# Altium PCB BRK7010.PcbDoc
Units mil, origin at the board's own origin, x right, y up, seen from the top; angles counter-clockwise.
Board outline 4724.41 x 3149.61 mil, 2 copper layers (Top Layer, Bottom Layer), stack 60.5 mil thick; 29 components, 139 nets, 372 pads, 81 vias.
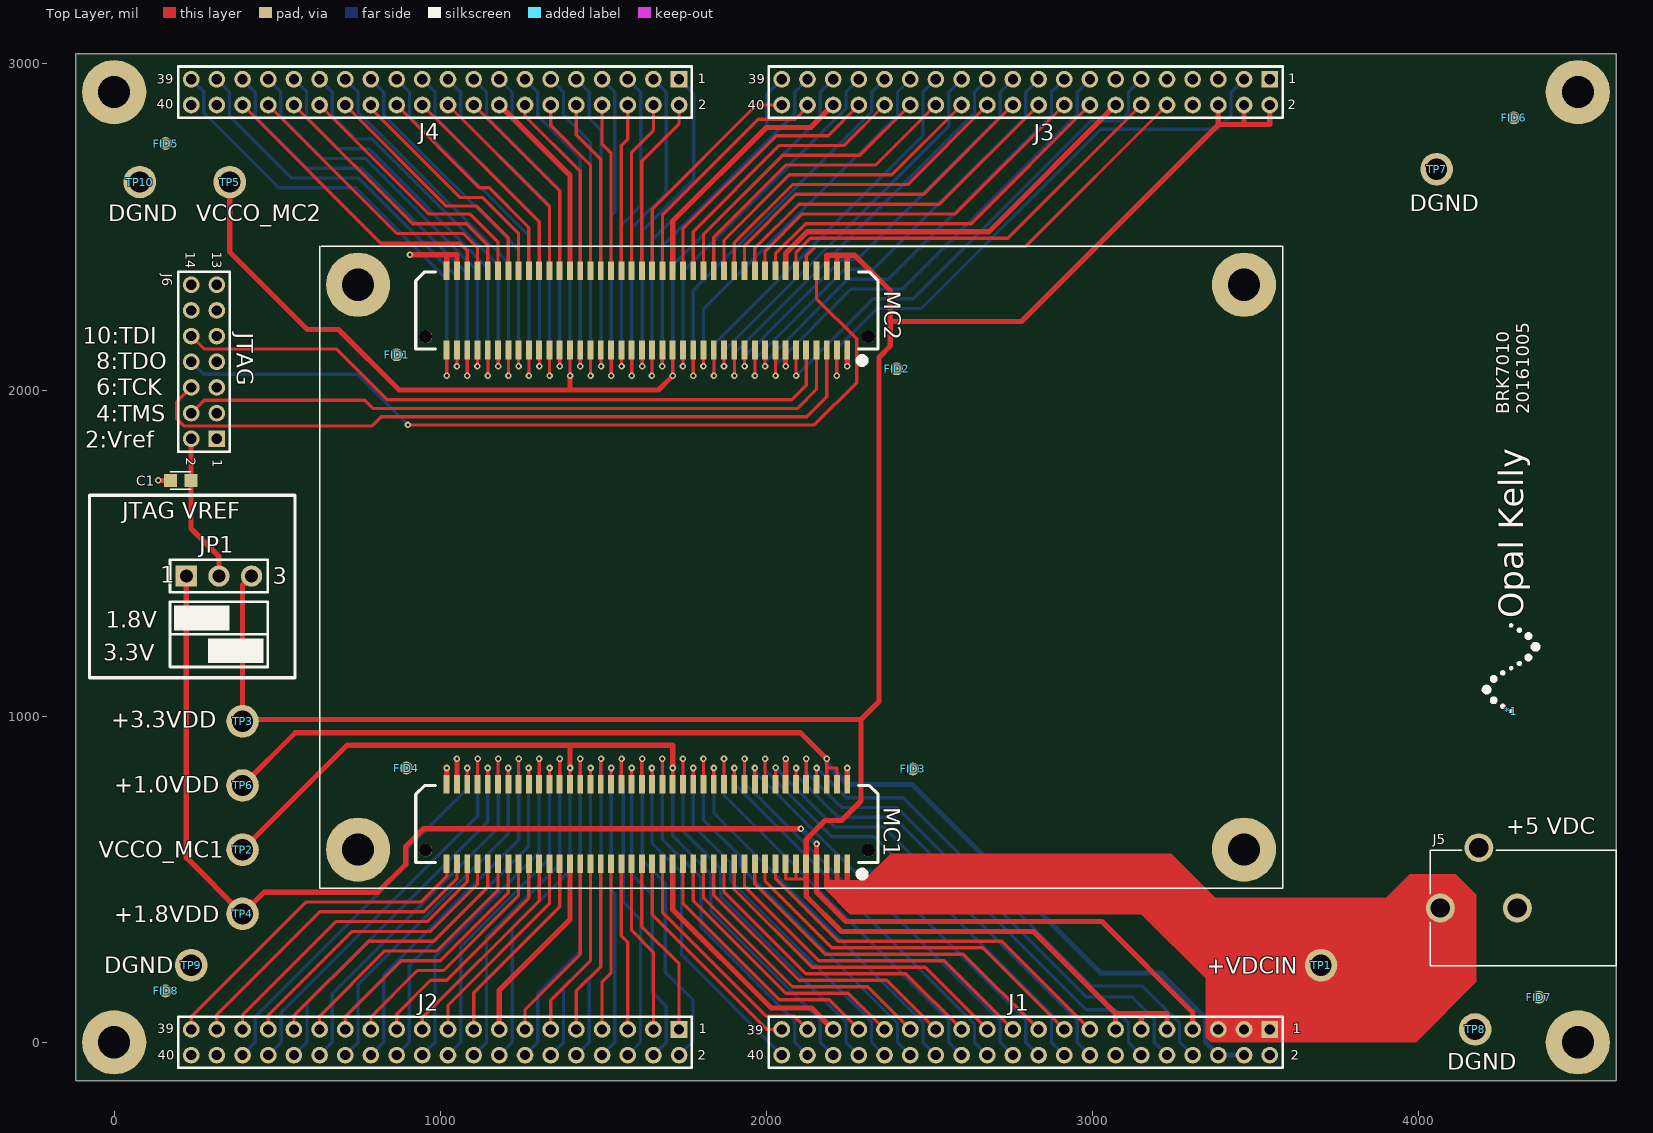
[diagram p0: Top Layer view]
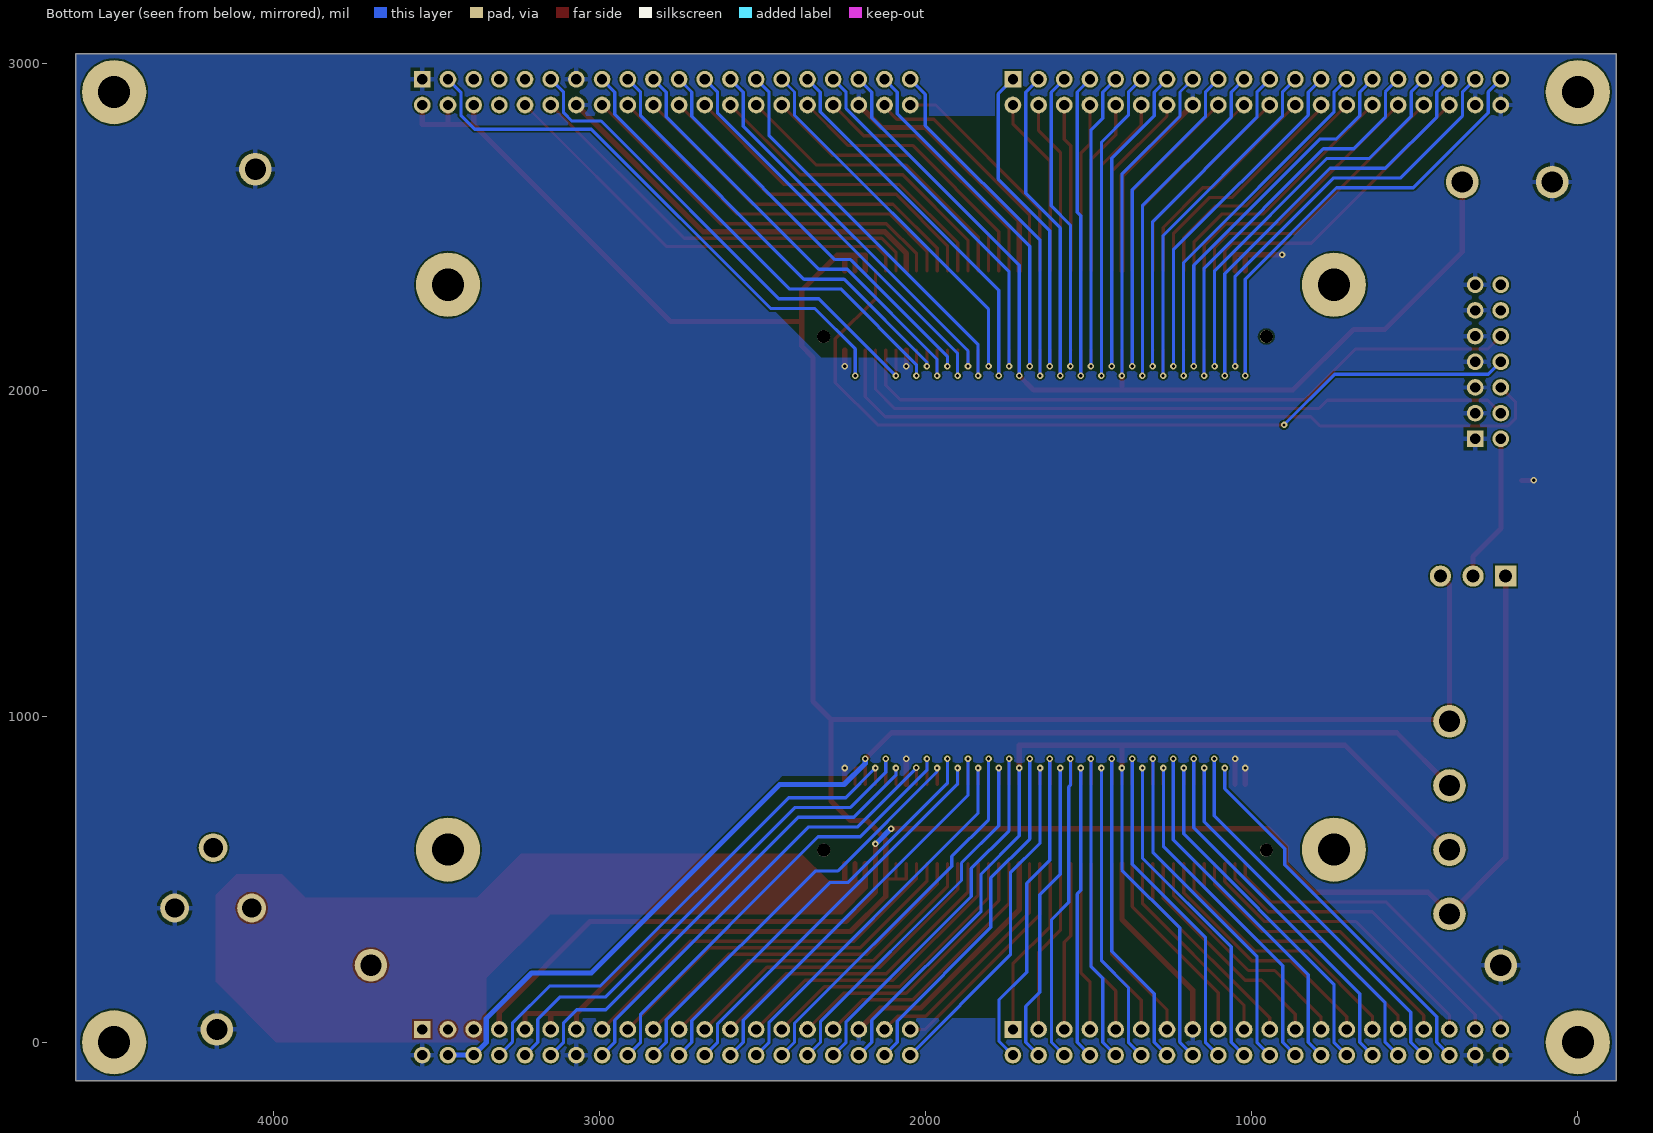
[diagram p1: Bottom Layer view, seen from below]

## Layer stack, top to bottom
Top Solder: solder mask 0.4, Solder Resist, Dk 3.5
Top Layer: signal copper 1.4
Dielectric1: core 57.7, IT-180A, Dk 4.8
Bottom Layer: signal copper 1.4
Bottom Solder: solder mask 0.4, Solder Resist, Dk 3.5

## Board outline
-118.11,-118.11 -118.11,3031.5 4606.3,3031.5 4606.3,-118.11

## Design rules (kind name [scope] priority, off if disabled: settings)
Clearance [All] p1: gap=5 ignorepadtopadclearanceinfootprint=FALSE except(0: Arc-Hole Track-Hole SMDPad-Hole THPad-Hole Via-Hole Fill-Hole Poly-Hole Region-Hole Text-Hole; 15: Fill-Fill Fill-Poly Fill-Region Poly-Poly Poly-Region Region-Region)
FabricationTestPointUsage TestPointUsage [All] p1: valid=0 allowmultiple=FALSE
FabricationTestpoint Testpoint [All] p1: side=3 testpointundercomponent=TRUE minsize=40 maxsize=100 preferedsize=60 minholesize=0 maxholesize=40 preferedholesize=32 testpointgrid=1 allowsidetop=TRUE allowsidebottom=TRUE usegrid=TRUE gridtolerance=0.01
HoleSize [All] p1: absolutevalues=TRUE maxlimit=236.22 minlimit=10 maxpercent=80.000 minpercent=20.000
MinimumSolderMaskSliver [All] p1: minsoldermaskwidth=3
PlaneConnect [All] p1: planeconnectstyle=Relief reliefexpansion=20 reliefentries=4 reliefconductorwidth=15 reliefairgap=10
PolygonConnect "Via Connect" [IsVia] p1: connectstyle=Direct reliefconductorwidth=10 reliefentries=4 polygonreliefangle="90 Angle" airgapwidth=10
PolygonConnect [All] p2: connectstyle=Relief reliefconductorwidth=15 reliefentries=4 polygonreliefangle="90 Angle" airgapwidth=10
RoutingVias [All] p1: holewidth=15 width=25 viastyle="Through Hole" minholewidth=10 minwidth=20 maxholewidth=50 maxwidth=100
SilkToSilkClearance [All] p1: silktosilkclearance=0.1
SilkToSolderMaskClearance SilkscreenOverComponentPads [IsPad] p1: minsilkscreentomaskgap=3 clearancetoexposedcopper=TRUE
SolderMaskExpansion [All] p1: expansion=4
Width okWidthPower [InNetClass('Power')] p1: maxlimit=100 minlimit=10 preferedwidth=10 minimp=50.000000 maximp=50.000000 favimp=50.000000
Width [All] p2: maxlimit=40 minlimit=6 preferedwidth=7 minimp=50.000000 maximp=50.000000 favimp=50.000000
23 further rules are at their usual default settings.

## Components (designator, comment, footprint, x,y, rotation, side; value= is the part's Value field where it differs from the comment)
*1 "Opal Kelly Logo" okLogo-23x5 4283.46,1015.75 r90 top
C1 "C0603C104K4RACTU" CAPC1608N 204,1723 r0 top value="0.1 u"
FID1 "FIDUCIAL" FID1MM/2MM-SS 866,2108 r90 top
FID2 "FIDUCIAL" FID1MM/2MM-SS 2399,2065 r90 top
FID3 "FIDUCIAL" FID1MM/2MM-SS 2449,838 r90 top
FID4 "FIDUCIAL" FID1MM/2MM-SS 896,841 r90 top
FID5 "FIDUCIAL" FID1MM/2MM-SS 157.48,2755.91 r90 top
FID6 "FIDUCIAL" FID1MM/2MM-SS 4291.34,2834.65 r90 top
FID7 "FIDUCIAL" FID1MM/2MM-SS 4369,138 r90 top
FID8 "FIDUCIAL" FID1MM/2MM-SS 157.48,157.48 r90 top
J1 "0877584016" HDR2X20-2MM 2795.28,0 r180 top locked
J2 "0877584016" HDR2X20-2MM 984.25,0 r180 top locked
J3 "0877584016" HDR2X20-2MM 2795.28,2913.39 r180 top locked
J4 "0877584016" HDR2X20-2MM 984.25,2913.39 r180 top locked
J5 "PJ-102AH" CUI-PJ102A 4605.83,411.5 r90 top
J6 "87831-1420" HDR2X7-2MM 275.59,2086.61 r90 top
JP1 "PBC03SAAN" HDR1X3 221.33,1429.58 r0 top
MC1 "BTE-040-01-F-D-A" BTE-040 1633.86,669.29 r180 top locked
MC2 "BTE-040-01-F-D-A" BTE-040 1633.86,2244.09 r180 top locked
TP1 "+VDCIN" TP-PTH-65/100 3700.79,236.22 r90 top
TP2 "VCCO_MC1" TP-PTH-65/100 393.7,590.55 r90 top
TP3 "+3.3VDD" TP-PTH-65/100 393.7,984.25 r90 top
TP4 "+1.8VDD" TP-PTH-65/100 393.7,393.7 r90 top
TP5 "VCCO_MC2" TP-PTH-65/100 354.33,2637.8 r90 top
TP6 "+1.0VDD" TP-PTH-65/100 393.7,787.4 r90 top
TP7 "DGND" TP-PTH-65/100 4055.12,2677.17 r90 top
TP8 "DGND" TP-PTH-65/100 4173.23,39.37 r90 top
TP9 "DGND" TP-PTH-65/100 236.22,236.22 r90 top
TP10 "DGND" TP-PTH-65/100 78.74,2637.8 r90 top

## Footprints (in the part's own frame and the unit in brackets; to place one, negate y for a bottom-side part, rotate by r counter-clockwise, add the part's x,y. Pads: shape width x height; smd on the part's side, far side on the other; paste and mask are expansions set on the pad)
BTE-040 [mm] "0.8mm Samtech socket"
  rect 0.46x1.45 smd: 1(-15.6,3.085) 2(-15.6,-3.085) 3(-14.8,3.085) 4(-14.8,-3.085) 5(-14,3.085) 6(-14,-3.085) 7(-13.2,3.085) 8(-13.2,-3.085) 9(-12.4,3.085) 10(-12.4,-3.085) 11(-11.6,3.085) 12(-11.6,-3.085) 13(-10.8,3.085) 14(-10.8,-3.085) 15(-10,3.085) 16(-10,-3.085) 17(-9.2,3.085) 18(-9.2,-3.085) 19(-8.4,3.085) 20(-8.4,-3.085) 21(-7.6,3.085) 22(-7.6,-3.085) 23(-6.8,3.085) 24(-6.8,-3.085) 25(-6,3.085) 26(-6,-3.085) 27(-5.2,3.085) 28(-5.2,-3.085) 29(-4.4,3.085) 30(-4.4,-3.085) 31(-3.6,3.085) 32(-3.6,-3.085) 33(-2.8,3.085) 34(-2.8,-3.085) 35(-2,3.085) 36(-2,-3.085) 37(-1.2,3.085) 38(-1.2,-3.085) 39(-0.4,3.085) 40(-0.4,-3.085) 41(0.4,3.085) 42(0.4,-3.085) 43(1.2,3.085) 44(1.2,-3.085) 45(2,3.085) 46(2,-3.085) 47(2.8,3.085) 48(2.8,-3.085) 49(3.6,3.085) 50(3.6,-3.085) 51(4.4,3.085) 52(4.4,-3.085) 53(5.2,3.085) 54(5.2,-3.085) 55(6,3.085) 56(6,-3.085) 57(6.8,3.085) 58(6.8,-3.085) 59(7.6,3.085) 60(7.6,-3.085) 61(8.4,3.085) 62(8.4,-3.085) 63(9.2,3.085) 64(9.2,-3.085) 65(10,3.085) 66(10,-3.085) 67(10.8,3.085) 68(10.8,-3.085) 69(11.6,3.085) 70(11.6,-3.085) 71(12.4,3.085) 72(12.4,-3.085) 73(13.2,3.085) 74(13.2,-3.085) 75(14,3.085) 76(14,-3.085) 77(14.8,3.085) 78(14.8,-3.085) 79(15.6,3.085) 80(15.6,-3.085)
  round 1.02 hole 1.02: 81(-17.235,2.035) 82(17.235,2.035)
  silkscreen extent -18,-3 18,4.15
CAPC1608N [mm] "Chip Capacitor, Body 1.6x0.8mm, IPC Medium Density"
  rect 1x1 smd: 1(-0.8,0) 2(0.8,0)
  silkscreen extent -0.8,-0.68 0.8,0.68, body extent -0.87,-0.48 0.87,0.48, height 0.85
CUI-PJ102A [mm] "2.1mm/5.5mm DC power jack"
  round 2.25 hole 1.5: 1(0,13.7) 2(0,7.7) 3(4.7,10.7)
  silkscreen extent -4.5,0 4.5,14.5
FID1MM/2MM-SS [mm] "Fiducial 1mm copper, 2mm soldermask, single-side"
  round 1 smd paste-0.5 mask+0.5: FID?(0,0)
HDR1X3 [mil] ".1\" 1x3 Header"
  rect 65x65 hole 40: 1(0,0)
  round 65 hole 40: 2(100,0) 3(200,0)
  silkscreen extent -50,-50 250,50
HDR2X7-2MM [mm] "2mm 2x7 header"
  rect 1.3x1.3 hole 0.8: 1(-6,-1)
  round 1.3 hole 0.8: 2(-6,1) 3(-4,-1) 4(-4,1) 5(-2,-1) 6(-2,1) 7(0,-1) 8(0,1) 9(2,-1) 10(2,1) 11(4,-1) 12(4,1) 13(6,-1) 14(6,1)
  silkscreen extent -7,-2 7,2
HDR2X20-2MM [mm] "2mm 2x20 header"
  rect 1.3x1.3 hole 0.8: 1(-19,-1)
  round 1.3 hole 0.8: 2(-19,1) 3(-17,-1) 4(-17,1) 5(-15,-1) 6(-15,1) 7(-13,-1) 8(-13,1) 9(-11,-1) 10(-11,1) 11(-9,-1) 12(-9,1) 13(-7,-1) 14(-7,1) 15(-5,-1) 16(-5,1) 17(-3,-1) 18(-3,1) 19(-1,-1) 20(-1,1) 21(1,-1) 22(1,1) 23(3,-1) 24(3,1) 25(5,-1) 26(5,1) 27(7,-1) 28(7,1) 29(9,-1) 30(9,1) 31(11,-1) 32(11,1) 33(13,-1) 34(13,1) 35(15,-1) 36(15,1) 37(17,-1) 38(17,1) 39(19,-1) 40(19,1)
  silkscreen extent -20,-2 20,2
okLogo-23x5 [mil] "Opal Kelly silkscreen logo (23mm x 5mm)"
  silkscreen extent -3,-82 266,82
TP-PTH-65/100 [mil] "Test point, plated through-hole, 65/100mil"
  round 100 hole 65: 1(0,0)

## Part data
*1: library part OKLOGO
C1: library part 000019, "Ceramic capacitor", Manufacturer=Kemet, ValueFloat=1E-7
FID1 FID2 FID3 FID4 FID5 FID6 FID7 FID8: "PCB fiducial"
J1 J2 J3 J4: library part 000583, "2mm header, 20x2, thru-hole", Manufacturer=Molex
J5: library part 000356, "DC power connector - high current", Manufacturer="CUI Inc."
J6: library part 000541, "2mm header, shrouded", Manufacturer=Molex
JP1: library part 001173, "Single-row header", Manufacturer="Sullins Electronics Corp."
MC1 MC2: library part 000059, "0.8mm high-density header", Manufacturer=Samtec
TP1 TP2 TP3 TP4 TP5 TP6 TP7 TP8 TP9 TP10: library part TP-PTH-65/100, "Test point, plated through-hole, 65/100mil"

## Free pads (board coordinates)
  round 196.85 hole 98.43: 0(0,0) 0(0,2913.39) 0(4488.19,0) 0(4488.19,2913.39) MH(748.03,590.55) MH(748.03,2322.83) MH(3464.57,590.55) MH(3464.57,2322.83)

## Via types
v1: diameter 20, hole 10, Top Layer to Bottom Layer, 81 vias

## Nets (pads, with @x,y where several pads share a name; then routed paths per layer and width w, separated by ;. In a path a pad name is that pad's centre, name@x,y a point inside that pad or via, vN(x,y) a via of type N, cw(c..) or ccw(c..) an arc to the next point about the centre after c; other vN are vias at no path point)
+1.0VDD: J1.4 J1.6 MC1.4 MC1.6 TP6.1 | length 3758.5
  Top Layer w10: MC1.6 2185.04,841 ; v1(2185,869) v1(2185,869) 2185.04,841 ; MC1.4 2216.54,841 2185.04,841
  Top Layer w16: TP6.1 555.3,949 2105,949 v1(2185,869)
  Bottom Layer w16: v1(2185,869) 2185,855 2250,790 2447,790 3025,212 3208,212 3347,73 3347,-0.54 J1.6 J1.4
+1.8VDD: J1.7 JP1.1 MC1.7 TP4.1 | length 4533.4
  Top Layer w16: JP1.1 221.33,566.07 TP4.1 460,460 808,460 894,546 894,600 949,655 v1(2106,655) ; v1(2154,608) 2153.54,607.54 MC1.7 2153.54,460.46 2244,370 3029,370 3307.09,91.91 J1.7
  Bottom Layer w16: v1(2106,655) 2153,608 v1(2154,608)
+3.3VDD: J1.9 J1.11 J1.13 J3.2 J3.4 J3.6 JP1.3 MC1.9 MC1.11 MC1.13 MC2.2 MC2.4 MC2.6 TP3.1 | length 7883
  Top Layer w10: MC1.13 2059.05,501 2090.55,501 ; MC1.11 2090.55,501 ; 2122.05,501 2090.55,501
  Top Layer w16: JP1.3 393.7,1401.95 TP3.1 399.45,990 2290,990 ; MC2.6 2185.04,2413 2216.54,2413 ; MC2.4 2216.54,2413 ; MC2.2 2248.03,2413 ; J1.13 3070.87,88.13 ; J1.11 3149.61,88.13 ; J1.9 3228.35,88.13 3149.61,88.13 ; J3.6 3385.83,2813.83 ; J3.4 3464.57,2813.83 ; J3.2 3543.31,2813.83 3464.57,2813.83 ; 2216.54,2413 2248.03,2413 ; 2248.03,2413 2272,2413 2380,2305 2380,2210 ; 2290,990 2345,1045 2345,2100 2380,2135 2380,2210 ; 2290,990 2290,740 2230,680 2180,680 2122.05,622.05 MC1.9 2122.05,501 2122.05,447.95 2230,340 2819,340 3070.87,88.13 ; 2380,2210 2782,2210 3385.83,2813.83 ; 3070.87,88.13 3149.61,88.13 ; 3385.83,2813.83 3464.57,2813.83
+VCCBATT: J3.3 MC2.3 | length 1793.6
  Top Layer w10: v1(2216,2044) 2216,2122.1 MC2.3
  Bottom Layer w10: v1(2216,2044) 2216,2126 2340,2250 2475,2250 3025,2800 3383,2800 3425,2842 3425,2913.19 J3.3
+VDCIN: J1.1 J1.3 J1.5 J5.1 MC1.1 MC1.3 MC1.5 TP1.1 | length 2346.7
  Top Layer w16: MC1.5 2185.04,480.96 2214,452 ; MC1.3 2216.54,454.54 2214,452 ; MC1.1 2248.03,426.03 2244,422 ; J5.1 3891.18,236.22 TP1.1 3515.01,422 2244,422 ; 2214,452 2244,422
DGND: C1.1 J1.2 J1.14 J1.35 J2.15 J2.38 J2.40 J3.1 J3.13 J3.14 J3.36 J4.16 J4.38 J4.40 J5.2 J6.1 J6.3 J6.5 J6.7 J6.9 J6.11 J6.13 MC1.2 MC1.14 MC1.35 MC1.55 MC1.78 MC1.80 MC2.1 MC2.13 MC2.14 MC2.36 MC2.56 MC2.78 MC2.80 TP7.1 TP8.1 TP9.1 TP10.1 | length 4663.9
  Top Layer w16: v1(135,1723) C1.1 ; v1(907,2415) 1018.11,2415 ; MC1.80 1019.68,840.68 v1(1020,841) ; MC2.80 1019.68,2415.71 1051.18,2415.71 MC2.78 ; v1(1051,869) 1051.18,868.82 MC1.78 ; J2.15 1181.1,160.1 1397.64,376.64 MC1.55 ; J4.16 1397.64,2657.48 MC2.56 ; MC1.35 1712.6,407.4 2015,105 2139.09,105 J1.35 ; MC2.36 1712.6,2517.6 2000,2805 2135.71,2805 J3.36 ; v1(2059,869) v1(2059,869) MC1.14 ; v1(2059,2073) 2059,2122.58 MC2.13 ; MC2.14 2059.05,2419.05 2125,2485 2681.85,2485 J3.14 ; MC1.2 v1(2248,841) ; v1(2248,2073) MC2.1@2248,2122.61
FPGA_TCK: J6.6 MC2.5 | length 2297.7
  Top Layer w10: J6.6 191,1962.65 191,1913 214,1890 791,1890 819,1918 2124.04,1918 2185.04,1979 MC2.5
FPGA_TDI: J6.10 MC2.9 | length 2093.6
  Top Layer w10: J6.10 275.57,2126 681,2126 837,1970 2078.05,1970 2122.05,2014 MC2.9
FPGA_TDO: J6.8 MC2.8 | length 2568.5
  Top Layer w10: v1(901,1893) 2147,1893 2277,2023 2277,2157 2153.54,2280.46 MC2.8
  Bottom Layer w10: J6.8 274.83,2048 746,2048 v1(901,1893)
FPGA_TMS: J6.4 MC2.7 | length 2089.9
  Top Layer w10: J6.4 276.09,1969 769,1969 795,1943 2095,1943 2153.54,2001.54 MC2.7
MC1_15: J1.15 MC1.15 | length 1201.8
  Top Layer w10: MC1.15 2027.56,502.44 2220,310 2721.5,310 J1.15
MC1_16: J1.16 MC1.16 | length 1420.6
  Top Layer w10: MC1.16 2027.56,840.56 v1(2029,842)
  Bottom Layer w10: v1(2029,842) 2029,840 2209,660 2360,660 2953,67 2953,-0.24 J1.16
MC1_17: J1.17 MC1.17 | length 1159.5
  Top Layer w10: MC1.17 1996.06,493.94 2200,290 2662.76,290 J1.17
MC1_18: J1.18 MC1.18 | length 1442.8
  Top Layer w10: v1(1996,869) v1(1996,869) MC1.18
  Bottom Layer w10: v1(1996,869) 1996,834 2200,630 2330,630 2874,86 2874,0.02 J1.18
MC1_19: J1.19 MC1.19 | length 1117.2
  Top Layer w10: MC1.19 1964.57,485.43 2180,270 2604.02,270 J1.19
MC1_20: J1.20 MC1.20 | length 1331.4
  Top Layer w10: MC1.20 1964.57,840.57 v1(1965,841)
  Bottom Layer w10: v1(1965,841) 1965,830 2270,525 2339,525 2795,69 2795,0.28 J1.20
MC1_21: J1.21 MC1.21 | length 1075
  Top Layer w10: MC1.21 1933.07,476.93 2160,250 2545.28,250 J1.21
MC1_22: J1.22 MC1.22 | length 1360.3
  Top Layer w10: v1(1933,869) 1933.07,868.93 MC1.22
  Bottom Layer w10: v1(1933,869) 1933,794 2237,490 2293,490 2717,66 2717,-0.46 J1.22
MC1_23: J1.23 MC1.23 | length 1032.7
  Top Layer w10: MC1.23 1901.57,468.43 2140,230 2486.54,230 J1.23
MC1_24: J1.24 MC1.24 | length 1251.9
  Top Layer w10: MC1.24 1901.57,840.57 v1(1902,841)
  Bottom Layer w10: v1(1902,841) 1902,793 2638,57 2638,-0.2 J1.24
MC1_25: J1.25 MC1.25 | length 990.5
  Top Layer w10: MC1.25 1870.08,459.92 2120,210 2427.8,210 J1.25
MC1_26: J1.26 MC1.26 | length 1288.4
  Top Layer w10: v1(1870,869) 1870.08,868.92 MC1.26
  Bottom Layer w10: v1(1870,869) 1870,757 2559,68 2559,0.06 J1.26
MC1_27: J1.27 MC1.27 | length 948.2
  Top Layer w10: MC1.27 1838.58,451.42 2100,190 2369.06,190 J1.27
MC1_28: J1.28 MC1.28 | length 1212.7
  Top Layer w10: MC1.28 1838.58,840.58 v1(1839,841)
  Bottom Layer w10: v1(1839,841) 1839,703 2480,62 2480,0.32 J1.28
MC1_29: J1.29 MC1.29 | length 905.9
  Top Layer w10: MC1.29 1807.09,442.91 2080,170 2310.32,170 J1.29
MC1_30: J1.30 MC1.30 | length 1249.2
  Top Layer w10: v1(1807,869) 1807.09,868.91 MC1.30
  Bottom Layer w10: v1(1807,869) 1807,683 1920,570 1920,540 2402,58 2402,-0.43 J1.30
MC1_31: J1.31 MC1.31 | length 863.7
  Top Layer w10: MC1.31 1775.59,434.41 2060,150 2251.57,150 J1.31
MC1_32: J1.32 MC1.32 | length 1173.6
  Top Layer w10: MC1.32 1775.59,840.59 v1(1776,841)
  Bottom Layer w10: v1(1776,841) 1776,664 1890,550 1890,496 2322,64 2322,0.83 J1.32
MC1_33: J1.33 MC1.33 | length 821.4
  Top Layer w10: MC1.33 1744.09,425.91 2040,130 2192.83,130 J1.33
MC1_34: J1.34 MC1.34 | length 1210.1
  Top Layer w10: v1(1744,869) 1744.09,868.91 MC1.34
  Bottom Layer w10: v1(1744,869) 1744,649 1860,533 1860,447 2244,63 2244,0.09 J1.34
MC1_37: J1.37 MC1.37 | length 742.7
  Top Layer w10: MC1.37 1681.1,398.9 2000,80 2085.35,80 J1.37
MC1_38: J1.38 MC1.38 | length 1171
  Top Layer w10: v1(1681,869) 1681.1,868.9 MC1.38
  Bottom Layer w10: v1(1681,869) 1681,623 1800,504 1800,352 2087,65 2087,-0.39 J1.38
MC1_39: J1.39 MC1.39 | length 700.5
  Top Layer w10: MC1.39 1649.61,390.39 2000.63,39.37 J1.39
MC1_40: J1.40 MC1.40 | length 1095.8
  Top Layer w10: v1(1649,841) 1649.61,840.39 MC1.40
  Bottom Layer w10: v1(1649,841) 1649,611 1740,520 1740,267.87 J1.40
MC1_41: J2.1 MC1.41 | length 555.8
  Top Layer w10: MC1.41 1618.11,354.89 1732.28,240.72 J2.1
MC1_42: J2.2 MC1.42 | length 1069.3
  Top Layer w10: MC1.42 1618.11,868.11 v1(1619,869)
  Bottom Layer w10: v1(1619,869) 1619,558 1690,487 1690,215 1775,130 1775,3.35 J2.2
MC1_43: J2.3 MC1.43 | length 536.2
  Top Layer w10: MC1.43 1586.61,343.39 1653.54,276.46 J2.3
MC1_44: J2.4 MC1.44 | length 991
  Top Layer w10: MC1.44 1586.61,840.61 v1(1587,841)
  Bottom Layer w10: v1(1587,841) 1587,515 1650,452 1650,153 1693,110 1693,0.09 J2.4
MC1_45: J2.5 MC1.45 | length 516.6
  Top Layer w10: MC1.45 1555.12,326.88 1574.8,307.2 J2.5
MC1_46: J2.6 MC1.46 | length 1027.2
  Top Layer w10: MC1.46 1555.12,868.12 v1(1556,869)
  Bottom Layer w10: v1(1556,869) 1556,788 1561,783 1561,429 1614,376 1614,-0.17 J2.6
MC1_47: J2.7 MC1.47 | length 519.9
  Top Layer w10: J2.7 1496.06,186.06 1523.62,213.62 MC1.47
MC1_48: J2.8 MC1.48 | length 951.5
  Top Layer w10: MC1.48 1523.62,840.62 v1(1524,841)
  Bottom Layer w10: J2.8 1535,-0.43 1535,455 1524,466 v1(1524,841)
MC1_49: J2.9 MC1.49 | length 539.4
  Top Layer w10: J2.9 1417.32,157.32 1492.13,232.13 MC1.49
MC1_50: J2.10 MC1.50 | length 1018.3
  Top Layer w10: MC1.50 1492.13,868.13 v1(1493,869)
  Bottom Layer w10: J2.10 1457,0.31 1457,197 1493,233 v1(1493,869)
MC1_51: J2.11 MC1.51 | length 559
  Top Layer w10: J2.11 1338.58,128.58 1460.63,250.63 MC1.51
MC1_52: J2.12 MC1.52 | length 981.5
  Top Layer w10: MC1.52 1460.63,840.63 v1(1461,841)
  Bottom Layer w10: J2.12 1378,0.05 1378,168 1461,251 v1(1461,841)
MC1_53: J2.13 MC1.53 | length 578.6
  Top Layer w10: J2.13 1259.84,99.84 1429.13,269.13 MC1.53
MC1_54: J2.14 MC1.54 | length 1056.7
  Top Layer w10: v1(1429,869) 1429.13,868.87 MC1.54
  Bottom Layer w10: J2.14 1299,-0.21 1299,149 1429,279 v1(1429,869)
MC1_57: J2.17 MC1.57 | length 617.7
  Top Layer w10: J2.17 1102.36,152.36 1366.14,416.14 MC1.57
MC1_58: J2.18 MC1.58 | length 1095.9
  Top Layer w10: v1(1366,869) 1366.14,868.86 MC1.58
  Bottom Layer w10: J2.18 1142,0.27 1142,322 1366,546 v1(1366,869)
MC1_59: J2.19 MC1.59 | length 637.3
  Top Layer w10: J2.19 1023.62,113.62 1334.65,424.65 MC1.59
MC1_60: J2.20 MC1.60 | length 1059.7
  Top Layer w10: MC1.60 1334.65,840.65 v1(1335,841)
  Bottom Layer w10: J2.20 1063,0.01 1063,293 1335,565 v1(1335,841)
MC1_61: J2.21 MC1.61 | length 656.9
  Top Layer w10: J2.21 944.88,74.88 1303.15,433.15 MC1.61
MC1_62: J2.22 MC1.62 | length 1135
  Top Layer w10: v1(1303,869) 1303.15,868.85 MC1.62
  Bottom Layer w10: J2.22 984,-0.25 984,264 1303,583 v1(1303,869)
MC1_63: J2.23 MC1.63 | length 705.7
  Top Layer w10: J2.23 866.14,86.14 970,190 1020,190 1271.65,441.65 MC1.63
MC1_64: J2.24 MC1.64 | length 1098.6
  Top Layer w10: v1(1270.79,841) 1271.65,840.13 MC1.64
  Bottom Layer w10: J2.24 905,-0.51 905,235 1270.79,600.79 v1(1270.79,841)
MC1_65: J2.25 MC1.65 | length 742.9
  Top Layer w10: J2.25 787.4,77.4 930,220 1010,220 1240.16,450.16 MC1.65
MC1_66: J2.26 MC1.66 | length 1174.7
  Top Layer w10: MC1.66 1240.16,868.37 v1(1240.79,869)
  Bottom Layer w10: J2.26 827,0.23 827,207 1240.79,620.79 v1(1240.79,869)
MC1_67: J2.27 MC1.67 | length 785.9
  Top Layer w10: J2.27 708.66,78.66 880,250 1000,250 1208.66,458.66 MC1.67
MC1_68: J2.28 MC1.68 | length 1137.8
  Top Layer w10: MC1.68 1208.66,840.87 v1(1208.79,841)
  Bottom Layer w10: J2.28 748,-0.03 748,178 1208.79,638.79 v1(1208.79,841)
MC1_69: J2.29 MC1.69 | length 828.9
  Top Layer w10: J2.29 629.92,79.92 830,280 990,280 1177.17,467.17 MC1.69
MC1_70: J2.30 MC1.70 | length 1213.8
  Top Layer w10: MC1.70 1177.17,868.38 v1(1177.79,869)
  Bottom Layer w10: J2.30 669,-0.29 669,149 1177.79,657.79 v1(1177.79,869)
MC1_71: J2.31 MC1.71 | length 871.9
  Top Layer w10: J2.31 551.18,81.18 780,310 980,310 1145.67,475.67 MC1.71
MC1_72: J2.32 MC1.72 | length 1177
  Top Layer w10: MC1.72 1145.67,840.88 v1(1145.79,841)
  Bottom Layer w10: J2.32 591,0.45 591,121 1145.79,675.79 v1(1145.79,841)
MC1_73: J2.33 MC1.73 | length 914.9
  Top Layer w10: J2.33 472.44,82.44 730,340 970,340 1114.17,484.17 MC1.73
MC1_74: J2.34 MC1.74 | length 1252.9
  Top Layer w10: MC1.74 1114.17,868.39 v1(1114.79,869)
  Bottom Layer w10: J2.34 512,0.19 512,92 1114.79,694.79 v1(1114.79,869)
MC1_75: J2.35 MC1.75 | length 957.9
  Top Layer w10: J2.35 393.7,83.7 680,370 960,370 1082.68,492.68 MC1.75
MC1_76: J2.36 MC1.76 | length 1216.1
  Top Layer w10: MC1.76 1082.68,840.89 v1(1082.79,841)
  Bottom Layer w10: J2.36 433,-0.07 433,78 899,544 899,594 1082.79,777.79 v1(1082.79,841)
MC1_77: J2.37 MC1.77 | length 1000.9
  Top Layer w10: J2.37 314.96,84.96 630,400 950,400 1051.18,501.18 MC1.77
MC1_79: J2.39 MC1.79 | length 1039.5
  Top Layer w10: J2.39 236.22,78.74 587.48,430 940,430 1019.68,509.68 MC1.79
MC2_10: J3.10 MC2.10 | length 1344.1
  Top Layer w10: MC2.10 2122.05,2412.05 2150,2440 2794.33,2440 J3.10
MC2_12: J3.12 MC2.12 | length 1301.9
  Top Layer w10: MC2.12 2090.55,2420.55 2135,2465 2740.59,2465 J3.12
MC2_15: J3.15 MC2.15 | length 1479.5
  Top Layer w10: MC2.15 2028,2122.2 v1(2028,2044)
  Bottom Layer w10: v1(2028,2044) 2028,2078 2260,2310 2418,2310 2953,2845 2953,2913.63 J3.15
MC2_16: J3.16 MC2.16 | length 1205.6
  Top Layer w10: MC2.16 2027.56,2417.56 2120,2510 2628.11,2510 J3.16
MC2_17: J3.17 MC2.17 | length 1381.5
  Top Layer w10: v1(1996,2073) 1996,2122.57 MC2.17
  Bottom Layer w10: v1(1996,2073) 1996,2086 2250,2340 2373,2340 2874,2841 2874,2913.37 J3.17
MC2_18: J3.18 MC2.18 | length 1163.4
  Top Layer w10: MC2.18 1996.06,2426.06 2110,2540 2579.37,2540 J3.18
MC2_19: J3.19 MC2.19 | length 1398.8
  Top Layer w10: MC2.19 1965,2122.2 v1(1965,2044)
  Bottom Layer w10: v1(1965,2044) 1965,2095 2240,2370 2327,2370 2795,2838 2795,2913.11 J3.19
MC2_20: J3.20 MC2.20 | length 1121.1
  Top Layer w10: MC2.20 1964.57,2434.57 2100,2570 2530.63,2570 J3.20
MC2_21: J3.21 MC2.21 | length 1298.4
  Top Layer w10: v1(1933,2073) 1933,2122.57 MC2.21
  Bottom Layer w10: v1(1933,2073) 1933,2103 2230,2400 2278,2400 2717,2839 2717,2913.85 J3.21
MC2_22: J3.22 MC2.22 | length 1078.9
  Top Layer w10: MC2.22 1933.07,2443.07 2090,2600 2481.89,2600 J3.22
MC2_23: J3.23 MC2.23 | length 1308.7
  Top Layer w10: MC2.23 1902,2122.21 v1(1902,2044)
  Bottom Layer w10: v1(1902,2044) 1902,2112 2638,2848 2638,2913.59 J3.23
MC2_24: J3.24 MC2.24 | length 1036.6
  Top Layer w10: MC2.24 1901.57,2451.57 2080,2630 2433.15,2630 J3.24
MC2_25: J3.25 MC2.25 | length 1231.1
  Top Layer w10: v1(1870,2073) 1870,2122.56 MC2.25
  Bottom Layer w10: v1(1870,2073) 1870,2120 2559,2809 2559,2913.33 J3.25
MC2_26: J3.26 MC2.26 | length 994.3
  Top Layer w10: MC2.26 1870.08,2460.08 2070,2660 2384.41,2660 J3.26
MC2_27: J3.27 MC2.27 | length 1269.5
  Top Layer w10: MC2.27 1839,2122.22 v1(1839,2044)
  Bottom Layer w10: v1(1839,2044) 1839,2139 2480,2780 2480,2913.07 J3.27
MC2_28: J3.28 MC2.28 | length 952.1
  Top Layer w10: MC2.28 1838.58,2468.58 2060,2690 2335.67,2690 J3.28
MC2_29: J3.29 MC2.29 | length 1192
  Top Layer w10: v1(1807,2073) 1807,2122.55 MC2.29
  Bottom Layer w10: v1(1807,2073) 1807,2247 2402,2842 2402,2913.81 J3.29
MC2_30: J3.30 MC2.30 | length 909.8
  Top Layer w10: MC2.30 1807.09,2477.09 2050,2720 2286.93,2720 J3.30
MC2_31: J3.31 MC2.31 | length 1230.4
  Top Layer w10: MC2.31 1776,2122.23 v1(1776,2044)
  Bottom Layer w10: v1(1776,2044) 1776,2306 2323,2853 2323,2913.55 J3.31
MC2_32: J3.32 MC2.32 | length 867.5
  Top Layer w10: MC2.32 1775.59,2485.59 2040,2750 2238.19,2750 J3.32
MC2_33: J3.33 MC2.33 | length 1152.9
  Top Layer w10: v1(1744,2073) 1744,2122.54 MC2.33
  Bottom Layer w10: v1(1744,2073) 1744,2362.96 2244,2862.96 2244,2913.29 J3.33
MC2_34: J3.34 MC2.34 | length 825.3
  Top Layer w10: MC2.34 1744.09,2494.09 2030,2780 2189.45,2780 J3.34
MC2_37: J3.37 MC2.37 | length 1113.8
  Top Layer w10: v1(1681,2073) 1681,2122.54 MC2.37
  Bottom Layer w10: v1(1681,2073) 1681,2441 2087,2847 2087,2913.77 J3.37
MC2_38: J3.38 MC2.38 | length 758.9
  Top Layer w10: MC2.38 1681.1,2536.1 1975,2830 2088,2830 2125.98,2867.98 J3.38
MC2_39: J3.39 MC2.39 | length 1152.6
  Top Layer w10: v1(1649,2044) 1649,2122.03 MC2.39
  Bottom Layer w10: v1(1649,2044) 1649,2459 2001,2811 2001,2906.51 J3.39
MC2_40: J3.40 MC2.40 | length 719
  Top Layer w10: MC2.40 1649.61,2554.61 1969.02,2874.02 J3.40
MC2_41: J4.1 MC2.41 | length 1013.7
  Top Layer w10: MC2.41 1619,2121.75 v1(1619,2073)
  Bottom Layer w10: v1(1619,2073) 1619,2489 1777,2647 1777,2908.04 J4.1
MC2_42: J4.2 MC2.42 | length 555.8
  Top Layer w10: MC2.42 1618.11,2702.11 1732.28,2816.28 J4.2
MC2_43: J4.3 MC2.43 | length 1047.8
  Top Layer w10: MC2.43 1587,2122.25 v1(1587,2044)
  Bottom Layer w10: v1(1587,2044) 1587,2497 1693,2603 1693,2913.3 J4.3
MC2_44: J4.4 MC2.44 | length 536.2
  Top Layer w10: MC2.44 1586.61,2728.61 1653.54,2795.54 J4.4
MC2_45: J4.5 MC2.45 | length 970.8
  Top Layer w10: MC2.45 1556,2121.75 v1(1556,2073)
  Bottom Layer w10: v1(1556,2073) 1556,2506 1615,2565 1615,2912.56 J4.5
MC2_46: J4.6 MC2.46 | length 516.6
  Top Layer w10: MC2.46 1555.12,2749.12 1574.8,2768.8 J4.6
MC2_47: J4.7 MC2.47 | length 1008.2
  Top Layer w10: MC2.47 1524,2122.26 v1(1524,2044)
  Bottom Layer w10: J4.7 1535,2913.82 1535,2545 1524,2534 v1(1524,2044)
MC2_48: J4.8 MC2.48 | length 519.9
  Top Layer w10: J4.8 1496.06,2753.94 1523.62,2726.38 MC2.48
MC2_49: J4.9 MC2.49 | length 961.1
  Top Layer w10: MC2.49 1493,2121.76 v1(1493,2073)
  Bottom Layer w10: J4.9 1457,2913.08 1457,2833 1493,2797 v1(1493,2073)
MC2_50: J4.10 MC2.50 | length 539.4
  Top Layer w10: J4.10 1417.32,2782.68 1492.13,2707.87 MC2.50
MC2_51: J4.11 MC2.51 | length 1038.3
  Top Layer w10: MC2.51 1461,2122.27 v1(1461,2044)
  Bottom Layer w10: J4.11 1378,2913.34 1378,2842 1461,2759 v1(1461,2044)
MC2_52: J4.12 MC2.52 | length 559
  Top Layer w10: J4.12 1338.58,2811.42 1460.63,2689.37 MC2.52
MC2_53: J4.13 MC2.53 | length 999.5
  Top Layer w10: v1(1429,2073) 1429,2122.5 MC2.53
  Bottom Layer w10: J4.13 1299,2913.6 1299,2841 1429,2711 v1(1429,2073)
MC2_54: J4.14 MC2.54 | length 578.6
  Top Layer w10: J4.14 1259.84,2840.16 1429.13,2670.87 MC2.54
MC2_57: J4.17 MC2.57 | length 1038.7
  Top Layer w10: v1(1366,2073) 1366,2122.5 MC2.57
  Bottom Layer w10: J4.17 1142,2913.12 1142,2838 1366,2614 v1(1366,2073)
MC2_58: J4.18 MC2.58 | length 617.7
  Top Layer w10: J4.18 1366.14,2610.24 MC2.58
MC2_59: J4.19 MC2.59 | length 1116.5
  Top Layer w10: MC2.59 1335,2122.28 v1(1335,2044)
  Bottom Layer w10: J4.19 1063,2913.38 1063,2837 1335,2565 v1(1335,2044)
MC2_60: J4.20 MC2.60 | length 637.3
  Top Layer w10: J4.20 1334.65,2562.99 MC2.60
MC2_61: J4.21 MC2.61 | length 1078.5
  Top Layer w10: MC2.61 1304,2121.79 v1(1304,2073)
  Bottom Layer w10: J4.21 984,2913.64 984,2836 1304,2516 v1(1304,2073)
MC2_62: J4.22 MC2.62 | length 656.9
  Top Layer w10: J4.22 1303.15,2515.75 MC2.62
MC2_63: J4.23 MC2.63 | length 1155.6
  Top Layer w10: MC2.63 1272,2122.29 v1(1272,2044)
  Bottom Layer w10: J4.23 906,2912.9 906,2839 1272,2473 v1(1272,2044)
MC2_64: J4.24 MC2.64 | length 693.9
  Top Layer w10: J4.24 1120.16,2620 1150,2620 1271.65,2498.35 MC2.64
MC2_65: J4.25 MC2.65 | length 1116.9
  Top Layer w10: v1(1240,2073) 1240,2122.48 MC2.65
  Bottom Layer w10: J4.25 827,2913.16 827,2843 1240,2430 v1(1240,2073)
MC2_66: J4.26 MC2.66 | length 736.4
  Top Layer w10: J4.26 787.4,2863.6 1061,2590 1130,2590 1240.16,2479.84 MC2.66
MC2_67: J4.27 MC2.67 | length 1194.8
  Top Layer w10: MC2.67 1209,2122.3 v1(1209,2044)
  Bottom Layer w10: J4.27 748,2913.42 748,2852 1209,2391 v1(1209,2044)
MC2_68: J4.28 MC2.68 | length 770.2
  Top Layer w10: J4.28 1018.68,2564 1112,2564 1208.66,2467.34 MC2.68
MC2_69: J4.29 MC2.69 | length 1186
  Top Layer w10: MC2.69 1178,2121.8 v1(1178,2073)
  Bottom Layer w10: J4.29 669,2913.68 669,2841 740,2770 790,2770 1178,2382 v1(1178,2073)
MC2_70: J4.30 MC2.70 | length 809
  Top Layer w10: J4.30 963.94,2540 1090,2540 1177.17,2452.83 MC2.70
MC2_71: J4.31 MC2.71 | length 1288.4
  Top Layer w10: MC2.71 1146,2122.31 v1(1146,2044)
  Bottom Layer w10: J4.31 590,2913.94 590,2836.97 686.97,2740 780,2740 1146,2374 v1(1146,2044)
MC2_72: J4.32 MC2.72 | length 851.2
  Top Layer w10: J4.32 915.2,2510 1080,2510 1145.67,2444.33 MC2.72
MC2_73: J4.33 MC2.73 | length 1271.4
  Top Layer w10: v1(1114,2073) 1114,2122.46 MC2.73
  Bottom Layer w10: J4.33 511,2914.2 511,2839 640,2710 770,2710 1114,2366 v1(1114,2073)
MC2_74: J4.34 MC2.74 | length 893.5
  Top Layer w10: J4.34 866.46,2480 1070,2480 1114.17,2435.83 MC2.74
MC2_75: J4.35 MC2.75 | length 1372.7
  Top Layer w10: MC2.75 1083.11,2122.2 v1(1083.11,2044)
  Bottom Layer w10: J4.35 433,2913.46 433,2837 590,2680 760,2680 1083.11,2356.89 v1(1083.11,2044)
MC2_76: J4.36 MC2.76 | length 935.8
  Top Layer w10: J4.36 817.72,2450 1060,2450 1082.68,2427.32 MC2.76
MC2_77: J4.37 MC2.77 | length 1355
  Top Layer w10: v1(1051,2073) 1051,2122.46 MC2.77
  Bottom Layer w10: J4.37 354,2913.72 354,2840 544,2650 750,2650 1051,2349 v1(1051,2073)
MC2_79: J4.39 MC2.79 | length 1449.8
  Top Layer w10: MC2.79 1020,2122.32 v1(1020,2044)
  Bottom Layer w10: J4.39 275,2913.98 275,2850 505,2620 740,2620 1020,2340 v1(1020,2044)
NetC1_2: C1.2 J6.2 JP1.2 | length 456.7
  Top Layer w16: J6.2 235.5,1849.68 235.5,1746 235.5,1575.5 321.33,1489.67 JP1.2
SYS_CLK_MC1: J1.8 MC1.8 | length 1601.7
  Top Layer w10: MC1.8 2153.54,840.54 v1(2154,841)
  Bottom Layer w10: v1(2154,841) 2245,750 2420,750 2997.5,172.5 3152.5,172.5 3267,58 3267,0.72 J1.8
SYS_CLK_MC2: J3.11 MC2.11 | length 1550.8
  Top Layer w10: MC2.11 2091,2122.19 v1(2091,2044)
  Bottom Layer w10: v1(2091,2044) 2327,2280 2450,2280 2995,2825 3085,2825 3110,2850 3110,2913.15 J3.11
VCCO_MC1: J1.36 J2.16 MC1.36 MC1.56 TP2.1 | length 3746.5
  Top Layer w10: MC1.56 1397.64,840.64 v1(1398,841) ; MC1.36 v1@1712.6,841.4
  Top Layer w16: TP2.1 714.15,911 1398,911 ; v1(1398,841) 1398,911 ; v1@1712.6,841.4 1712.6,911 1398,911
  Bottom Layer w10: J2.16 1221,0.53 1221,351 1398,528 v1(1398,841) ; v1(1713,841) 1713,633 1830,516 1830,402 2165,67 2165,0.35 J1.36
VCCO_MC2: J3.35 J4.15 MC2.35 MC2.55 TP5.1 | length 4079.1
  Top Layer w10: MC2.55 1398,2122.27 v1(1398,2044) ; MC2.35 1713,2122.24 v1(1713,2044)
  Top Layer w16: TP5.1 354.33,2423.67 592,2186 688,2186 874,2000 1398,2000 ; v1(1398,2044) 1398,2000 ; v1(1713,2044) 1669,2000 1398,2000
  Bottom Layer w10: J4.15 1220,2913.86 1220,2840 1398,2662 v1(1398,2044) ; v1(1713,2044) 1713,2383 2165,2835 2165,2913.03 J3.35
XADC_VN: J1.10 MC1.10 | length 1625.9
  Top Layer w10: v1(2122,869) v1(2122,869) MC1.10
  Bottom Layer w10: v1(2122,869) 2122,828 2230,720 2400,720 2981,139 3120,139 3189,70 3189,-0.02 J1.10
XADC_VP: J1.12 MC1.12 | length 1521.6
  Top Layer w10: MC1.12 2090.55,840.55 v1(2091,841)
  Bottom Layer w10: v1(2091,841) 2091,819 2220,690 2391,690 2981,100 3070,100 3110,60 3110,0.24 J1.12
pads on no net: FID1.FID? FID2.FID? FID3.FID? FID4.FID? FID5.FID? FID6.FID? FID7.FID? FID8.FID? J3.5 J3.7 J3.8 J3.9 J5.3 J6.12 J6.14 MC1.81 MC1.82 MC2.81 MC2.82

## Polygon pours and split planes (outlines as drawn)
DGND on Bottom Layer "L2-DGND" (solid, remove dead copper, pour order 1000): -118.11,3031.5 -118.11,-118.11 4606.3,-118.11 4606.3,3031.5

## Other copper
Top Layer:
  region net +VDCIN: 4114.17,515.75 3972.44,515.75 3900.58,443.89 3375.89,443.89 3241.89,577.89 2380.89,577.89 2299.06,496.06 2177.17,496.06 2177.17,471.61 2255.78,393 3149.78,393 3346.46,196.32 3346.46,15.75 3362.21,0 3992.13,0 4177.17,185.04 4177.17,452.76
Bottom Layer:
  pour cut-out: 280,2840 500,2620 740,2620 1020,2340 1020,2100 2320,2100 3060,2840
  pour cut-out: 3180,75 2440,815 1150,815 410,75

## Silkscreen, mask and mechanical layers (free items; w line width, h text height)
Top Overlay:
  rectangle: 287.33,1162.58 458.33,1238.58
  rectangle: 183.33,1262.58 354.33,1338.58
  lines w4.72: 629.92,2440.95 629.92,472.44 3582.68,472.44 3582.68,2440.95 635,2440.95
  lines w8: 171.33,1250.58 171.33,1150.58 471.33,1150.58 471.33,1250.58 ; 171.33,1250.58 471.33,1250.58 ; 171.33,1250.58 171.33,1350.58 471.33,1350.58 471.33,1250.58
  lines w10: -75.67,1117.58 -75.67,1677.58 554.33,1677.58 554.33,1117.58 -75.67,1117.58
  text "JTAG" at 376,2176 h50 r270
  text "10:TDI" at -96,2142.37 h50
  text "8:TDO" at -55.54,2063.22 h50
  text "6:TCK" at -55.54,1983.22 h50
  text "BRK7010 / 20161005" at 4338.58,1925.2 h40 r90
  text "4:TMS" at -55.54,1903.22 h50
  text "2:Vref" at -88.87,1823.22 h50
  text "JTAG VREF" at 25.33,1605.58 h50
  text "1.8V" at -25.67,1270.58 h50
  text "3.3V" at -33.67,1170.58 h50
  text "+5 VDC" at 4268,638 h50
Top Solder:
  the board outline again, w1
Outline:
  the board outline again, w8
Mechanical:
  lines w10: 629.92,472.44 629.92,2440.94 3582.68,2440.94 3582.68,472.44 629.92,472.44
Fab Notes:
  drawing of 191 lines, arcs and shapes, not listed
  text "Layer" at 5264.95,3489 h50
  text "Name" at 5609.88,3489 h50
  text "Material" at 6388,3489 h50
  text "Thickness" at 7107.81,3489 h50
  text "Constant" at 7652.67,3489 h50
  text "Board Layer Stack" at 8130.89,3489 h50
  text "NOTES /  / 1. MATERIAL SELECTION: /      2-LAYER, IT-180A OR EQUIVALENT, 62 MILS +/-10% THICK /      SURFACE FINISH: ENIG (ELECTROLESS NICKEL, IMMERSION GOLD) /  / 2. SOLDER RESIST: GREEN LPI /  / 3. SILKSCREEN: WHITE / DO NOT REMOVE OVER TENTED VIAS /  / 4. LOT CODE IDENTIFICATION: ADD TO SILKSCREEN /  / 5. DRILL SIZES ARE FINISHED SIZE AFTER PLATING /  / 6. ELECTRICAL BARE BOARD TEST REQUIRED /       / 7. PANELIZATION: /      1 PIECE PER ARRAY /      0.25-IN RAILS ON ALL SIDES /      0.25-IN TAB ROUTING WITH MOUSE-BITES FOR BOARD SEPARATION /      MOUSE BITE LOCATIONS INDICATED BY ::: /       / 8. ALL 10.00-MIL VIAS MUST BE PLATED OVER FILLED VIA (POFV) /       / 9. FABRICATE TO MEET EU ROHS DIRECTIVE /  / 10. UL CERTIFICATION MARK REQUIRED" at -428,3424 h50
  text "Top Overlay" at 5609.88,3389 h50
  text "Top Solder" at 5609.88,3289 h50
  text "Solder Resist" at 6388,3289 h50
  text "0.40mil" at 7107.81,3289 h50
  text "3.5" at 7652.67,3289 h50
  text "1" at 5264.95,3189 h50
  text "Top Layer" at 5609.88,3189 h50
  text "Copper" at 6388,3189 h50
  text "1.40mil" at 7107.81,3189 h50
  text "Dielectric1" at 5609.88,3089 h50
  text "IT-180A" at 6388,3089 h50
  text "57.70mil" at 7107.81,3089 h50
  text "4.8" at 7652.67,3089 h50
  text ":::" at 3591.89,3064.89 h50
  text ":::" at 1799,3064 h50
  text "2" at 5264.95,2989 h50
  text "Bottom Layer" at 5609.88,2989 h50
  text "Copper" at 6388,2989 h50
  text "1.40mil" at 7107.81,2989 h50
  text "Bottom Solder" at 5609.88,2889 h50
  text "Solder Resist" at 6388,2889 h50
  text "0.40mil" at 7107.81,2889 h50
  text "3.5" at 7652.67,2889 h50
  text "Bottom Overlay" at 5609.88,2789 h50
  text ":::" at -155.11,1419.89 h50 r90
  text ":::" at 4672.89,1414.89 h50 r90
  text ":::" at 1790,-179 h50
  text ":::" at 3602.89,-184.11 h50
Drill Drawing:
  lines w10: 3662.52,4330.89 3676.41,4330.89 3690.29,4317 3704.18,4330.89 3718.07,4330.89 3704.18,4344.78 3718.07,4358.67 3704.18,4358.67 3690.29,4372.56 3676.41,4358.67 3662.52,4358.67 3676.41,4344.78 3662.52,4330.89 ; 3662.52,4497.56 3718.07,4497.56 3690.29,4442 3662.52,4497.56 ; 3662.52,4567 3718.07,4567 3718.07,4622.56 3662.52,4622.56 3662.52,4567 ; 3662.52,4719.78 3690.29,4692 3718.07,4719.78 3690.29,4747.56 3662.52,4719.78 ; 3662.52,4817 3662.52,4830.89 3676.41,4844.78 3662.52,4858.67 3662.52,4872.56 3676.41,4872.56 3690.29,4858.67 3704.18,4872.56 3718.07,4872.56 3718.07,4858.67 3704.18,4844.78 3718.07,4830.89 3718.07,4817 3704.18,4817 3690.29,4830.89 3676.41,4817 3662.52,4817 ; 3662.52,4942 3690.29,4955.89 3718.07,4942 3704.18,4969.78 3718.07,4997.56 3690.29,4983.67 3662.52,4997.56 3676.41,4969.78 3662.52,4942 ; 3662.52,5080.89 3676.41,5080.89 3676.41,5067 3704.18,5067 3704.18,5080.89 3718.07,5080.89 3718.07,5108.67 3704.18,5108.67 3704.18,5122.56 3676.41,5122.56 3676.41,5108.67 3662.52,5108.67 3662.52,5080.89 ; 3673.63,4336.44 3681.96,4336.44 3690.29,4328.11 3698.63,4336.44 3706.96,4336.44 3698.63,4344.78 3706.96,4353.11 3698.63,4353.11 3690.29,4361.44 3681.96,4353.11 3673.63,4353.11 3681.96,4344.78 3673.63,4336.44 ; 3673.63,4486.44 3706.96,4486.44 3690.29,4453.11 3673.63,4486.44 ; 3673.63,4578.11 3706.96,4578.11 3706.96,4611.44 3673.63,4611.44 3673.63,4578.11 ; 3673.63,4828.11 3673.63,4836.44 3681.96,4844.78 3673.63,4853.11 3673.63,4861.44 3681.96,4861.44 3690.29,4853.11 3698.63,4861.44 3706.96,4861.44 3706.96,4853.11 3698.63,4844.78 3706.96,4836.44 3706.96,4828.11 3698.63,4828.11 3690.29,4836.44 3681.96,4828.11 3673.63,4828.11 ; 3673.63,4953.11 3690.29,4961.44 3706.96,4953.11 3698.63,4969.78 3706.96,4986.44 3690.29,4978.11 3673.63,4986.44 3681.96,4969.78 3673.63,4953.11 ; 3673.63,5086.44 3681.96,5086.44 3681.96,5078.11 3698.63,5078.11 3698.63,5086.44 3706.96,5086.44 3706.96,5103.11 3698.63,5103.11 3698.63,5111.44 3681.96,5111.44 3681.96,5103.11 3673.63,5103.11 3673.63,5086.44
  lines w15: 3612.17,4279.5 9007.38,4279.5 ; 3612.17,5154.5 9007.38,5154.5 ; 4076.57,4154.5 4076.57,5279.5 ; 4579.77,4154.5 4579.77,5279.5 ; 5499.5,4154.5 5499.5,5279.5 ; 5926.4,4154.5 5926.4,5279.5 ; 6543.23,4154.5 6543.23,5279.5 ; 7796.19,4154.5 7796.19,5279.5 ; 8293.06,4154.5 8293.06,5279.5 ; 3612.17,4154.5 9007.38,4154.5 9007.38,5279.5 3612.17,5279.5 3612.17,4154.5
  text "Symbol" at 3687.17,5192 h60
  text "Count" at 4114.07,5192 h60
  text "Hole Size" at 4617.27,5192 h60
  text "Plated" at 5537,5192 h60
  text "Hole Type" at 5963.9,5192 h60
  text "Drill Layer Pair" at 6580.73,5192 h60
  text "Via/Pad" at 7833.69,5192 h60
  text "Technology" at 8330.56,5192 h60
  text "81" at 4114.07,5067 h50
  text "10.00mil (0.254mm)" at 4617.27,5067 h50
  text "PTH" at 5537,5067 h50
  text "Round" at 5963.9,5067 h50
  text "Top Layer - Bottom Layer" at 6580.73,5067 h50
  text "Via" at 7833.69,5067 h50
  text "v51h25" at 8330.56,5067 h50
  text "174" at 4114.07,4942 h50
  text "31.50mil (0.800mm)" at 4617.27,4942 h50
  text "PTH" at 5537,4942 h50
  text "Round" at 5963.9,4942 h50
  text "Top Layer - Bottom Layer" at 6580.73,4942 h50
  text "Pad" at 7833.69,4942 h50
  text "(Mixed)" at 8330.56,4942 h50
  text "3" at 4114.07,4817 h50
  text "40.00mil (1.016mm)" at 4617.27,4817 h50
  text "PTH" at 5537,4817 h50
  text "Round" at 5963.9,4817 h50
  text "Top Layer - Bottom Layer" at 6580.73,4817 h50
  text "Pad" at 7833.69,4817 h50
  text "(Mixed)" at 8330.56,4817 h50
  text "4" at 4114.07,4692 h50
  text "40.16mil (1.020mm)" at 4617.27,4692 h50
  text "PTH" at 5537,4692 h50
  text "Round" at 5963.9,4692 h50
  text "Top Layer - Bottom Layer" at 6580.73,4692 h50
  text "Pad" at 7833.69,4692 h50
  text "c102h102" at 8330.56,4692 h50
  text "3" at 4114.07,4567 h50
  text "59.06mil (1.500mm)" at 4617.27,4567 h50
  text "PTH" at 5537,4567 h50
  text "Round" at 5963.9,4567 h50
  text "Top Layer - Bottom Layer" at 6580.73,4567 h50
  text "Pad" at 7833.69,4567 h50
  text "c225h150" at 8330.56,4567 h50
  text "10" at 4114.07,4442 h50
  text "65.00mil (1.651mm)" at 4617.27,4442 h50
  text "PTH" at 5537,4442 h50
  text "Round" at 5963.9,4442 h50
  text "Top Layer - Bottom Layer" at 6580.73,4442 h50
  text "Pad" at 7833.69,4442 h50
  text "c254h165" at 8330.56,4442 h50
  text "8" at 4114.07,4317 h50
  text "98.43mil (2.500mm)" at 4617.27,4317 h50
  text "PTH" at 5537,4317 h50
  text "Round" at 5963.9,4317 h50
  text "Top Layer - Bottom Layer" at 6580.73,4317 h50
  text "Pad" at 7833.69,4317 h50
  text "c500h250" at 8330.56,4317 h50
  text "283 Total" at 4114.07,4192 h50
Doc-Assy-Top:
  lines w2.94: -926.35,-90.51 -808.65,-90.51 ; -926.35,1160.03 -808.65,1160.03 ; -926.35,2410.57 -808.65,2410.57 ; 574.3,-1223.35 574.3,-1105.65 ; 574.3,3425.71 574.3,3543.4 ; 2192.64,-1223.35 2192.64,-1105.65 ; 2192.64,3425.71 2192.64,3543.4 ; 2663.43,-1223.35 5311.62,-1223.35 ; 3430.32,-1105.74 3430.32,-686.1 5193.93,-686.1 ; 3430.32,-964.13 5193.93,-964.13 ; 3696.46,-1105.74 3696.46,-964.13 ; 3810.98,-1223.35 3810.98,-1105.65 ; 3810.98,3425.71 3810.98,3543.4 ; 4109.38,-1105.74 4109.38,-964.13 ; 4191.94,-963.95 4191.94,-686.1 ; 4719.77,-1105.74 4719.77,-964.13 ; 5193.93,-90.51 5311.62,-90.51 ; 5193.93,1160.03 5311.62,1160.03 ; 5193.93,2410.57 5311.62,2410.57 ; 5311.62,-1223.35 -926.35,-1223.35 -926.35,3543.4 5311.62,3543.4 5311.62,-1223.35 ; -808.65,-1105.65 5193.93,-1105.65 5193.93,3425.71 -808.65,3425.71 -808.65,-1105.65
  text "1" at -248.8,3465.81 h41.19
  text "2" at 1369.93,3465.81 h41.19
  text "3" at 2985.33,3465.81 h41.19
  text "4" at 4604.27,3465.81 h41.19
  text "A" at -884.07,2982.58 h41.19
  text "A" at 5239.92,2982.58 h41.19
  text "B" at -884.07,1732.04 h41.19
  text "B" at 5239.92,1732.04 h41.19
  text "C" at -884.07,481.5 h41.19
  text "C" at 5239.92,481.5 h41.19
  text "TITLE:" at 3476.02,-732.44 h26.48
  text "Opal Kelly" at 4238.27,-750.97 h41.19
  text "D" at -884.07,-766.09 h41.19
  text "D" at 5239.92,-766.09 h41.19
  text "13500 SW 72nd Ave Suite 100" at 4238.27,-820.48 h41.19
  text "Portland, OR 97223" at 4238.27,-878.4 h41.19
  text "BRK7010 / Assembly Drawing" at 3495.07,-879.39 h41.19
  text "www.opalkelly.com" at 4238.27,-936.32 h41.19
  text "(Top)" at 3495.07,-946.48 h41.19
  text "REV:" at 3463.07,-1003.37 h26.48
  text "SIZE:" at 3732.37,-1003.37 h26.48
  text "ENGINEER:" at 4145.28,-1003.37 h26.48
  text "DATE:" at 4755.68,-1003.37 h26.48
  text "A01" at 3498.98,-1075.18 h41.19
  text "ANSI A" at 3768.27,-1075.18 h41.19
  text "NDK" at 4181.19,-1075.18 h41.19
  text ".PRINT_DATE" at 4791.59,-1075.18 h41.19
  text "1" at -248.8,-1186.95 h41.19
  text "2" at 1369.93,-1186.95 h41.19
  text "3" at 2985.33,-1186.95 h41.19
  text "4" at 4604.27,-1186.95 h41.19
Doc-Assy-Bot:
  lines w2.94: -927.05,-90.86 -809.33,-90.86 ; -927.05,1159.88 -809.33,1159.88 ; -927.05,2410.62 -809.33,2410.62 ; -809.33,-964.48 953.77,-964.48 ; -809.33,-686.53 953.77,-686.53 953.77,-1106.05 ; -335.32,-1106.05 -335.32,-964.48 ; 192.37,-964.3 192.37,-686.53 ; 274.91,-1106.05 274.91,-964.48 ; 573.84,-1223.88 573.84,-1106.16 ; 573.84,3425.92 573.84,3543.64 ; 687.7,-1106.05 687.7,-964.48 ; 1721.57,-1223.88 -927.05,-1223.88 ; 2192.44,-1223.88 2192.44,-1106.16 ; 2192.44,3425.92 2192.44,3543.64 ; 3811.04,-1223.88 3811.04,-1106.16 ; 3811.04,3425.92 3811.04,3543.64 ; 5194.21,-90.86 5311.93,-90.86 ; 5194.21,1159.88 5311.93,1159.88 ; 5194.21,2410.62 5311.93,2410.62 ; -927.05,-1223.88 5311.93,-1223.88 5311.93,3543.64 -927.05,3543.64 -927.05,-1223.88 ; -809.33,-1106.16 5194.21,-1106.16 5194.21,3425.92 -809.33,3425.92 -809.33,-1106.16
  text "4" at -219.58,3466.03 h41.2
  text "3" at 1399.62,3466.03 h41.2
  text "2" at 3015.28,3466.03 h41.2
  text "1" at 4634.27,3466.03 h41.2
  text "A" at -855.33,2982.72 h41.2
  text "A" at 5269.64,2982.72 h41.2
  text "B" at -855.33,1731.98 h41.2
  text "B" at 5269.64,1731.98 h41.2
  text "C" at -855.33,481.24 h41.2
  text "C" at 5269.64,481.24 h41.2
  text "TITLE:" at 908.08,-732.86 h26.47
  text "Opal Kelly" at 146.05,-751.39 h41.18
  text "D" at -855.33,-766.55 h41.2
  text "D" at 5269.64,-766.55 h41.2
  text "13500 SW 72nd Ave Suite 100" at 146.05,-820.87 h41.18
  text "Portland, OR 97223" at 146.05,-878.78 h41.18
  text "BRK7010 / Assembly Drawing" at 889.04,-879.77 h41.18
  text "www.opalkelly.com" at 146.05,-936.68 h41.18
  text "(Bottom)" at 889.04,-946.84 h41.18
  text "DATE:" at -371.21,-1003.71 h26.47
  text "ENGINEER:" at 239.01,-1003.71 h26.47
  text "SIZE:" at 651.81,-1003.71 h26.47
  text "REV:" at 921.02,-1003.71 h26.47
  text ".PRINT_DATE" at -407.11,-1075.5 h41.18
  text "NDK" at 203.12,-1075.5 h41.18
  text "ANSI A" at 615.91,-1075.5 h41.18
  text "A01" at 885.13,-1075.5 h41.18
  text "4" at -219.58,-1187.48 h41.2
  text "3" at 1399.62,-1187.48 h41.2
  text "2" at 3015.28,-1187.48 h41.2
  text "1" at 4634.27,-1187.48 h41.2
Doc-Fab:
  lines w5: -978.46,164.75 -778.46,164.75 ; -978.46,2289.75 -778.46,2289.75 ; -978.46,4414.75 -778.46,4414.75 ; 1571.54,-1760.25 1571.54,-1560.25 ; 1571.54,6139.75 1571.54,6339.75 ; 4321.54,-1760.25 4321.54,-1560.25 ; 4321.54,6139.75 4321.54,6339.75 ; 4882.35,-1560.25 4882.35,-504.11 9421.54,-504.11 ; 4882.35,-694.11 6642.35,-694.11 ; 4882.35,-584.11 6642.35,-584.11 ; 5121.54,-1760.25 9621.54,-1760.25 ; 5302.35,-1560.25 5302.35,-504.11 ; 6642.35,-1560.25 6642.35,-504.11 ; 6642.35,-1364.11 9422.35,-1364.11 ; 6642.35,-924.11 9421.54,-924.11 ; 7071.54,-1760.25 7071.54,-1560.25 ; 7071.54,6139.75 7071.54,6339.75 ; 7202.35,-1560.25 7202.35,-1364.11 ; 7882.35,-1364.11 7882.35,-924.11 ; 8532.35,-1560.25 8532.35,-1364.11 ; 9421.54,164.75 9621.54,164.75 ; 9421.54,2289.75 9621.54,2289.75 ; 9421.54,4414.75 9621.54,4414.75 ; 9621.54,-1760.25 -978.46,-1760.25 -978.46,6339.75 9621.54,6339.75 9621.54,-1760.25 ; -778.46,-1560.25 9421.54,-1560.25 9421.54,6139.75 -778.46,6139.75 -778.46,-1560.25
  text "1" at 172.88,6207.9 h70
  text "2" at 2923.54,6207.9 h70
  text "3" at 5668.54,6207.9 h70
  text "4" at 8419.55,6207.9 h70
  text "A" at -906.61,5386.75 h70
  text "A" at 9499.69,5386.75 h70
  text "B" at -906.61,3261.75 h70
  text "B" at 9499.69,3261.75 h70
  text "C" at -906.61,1136.75 h70
  text "C" at 9499.69,1136.75 h70
  text "REVISION:" at 4911.35,-564.11 h40
  text "DESCRIPTION:" at 5341.35,-564.11 h40
  text "PART NUMBER:" at 6722.35,-644.11 h75
  text "20161005" at 4912.35,-664.11 h50
  text "Initial Release" at 5342.35,-664.11 h50
  text "BRK7010PCB-20161005" at 6742.35,-924.11 h130
  text "D" at -906.61,-983.25 h70
  text "D" at 9499.69,-983.25 h70
  text "TITLE:" at 6702.35,-1004.11 h40
  text "Opal Kelly" at 7942.35,-1024.11 h60
  text "13500 SW 72nd Ave Suite 100" at 7942.35,-1124.11 h60
  text "Portland, OR 97223" at 7942.35,-1224.11 h60
  text "XEM7010 / Fabrication Drawing" at 6742.35,-1304.11 h60
  text "www.opalkelly.com" at 7942.35,-1324.11 h60
  text "SIZE:" at 6702.35,-1424.11 h40
  text "ENGINEER:" at 7262.35,-1424.11 h40
  text "DATE:" at 8582.35,-1424.11 h40
  text "ANSI A" at 6742.35,-1524.11 h60
  text "NDK" at 7302.35,-1524.11 h60
  text ".PRINT_DATE" at 8622.35,-1524.11 h60
  text "1" at 172.88,-1698.4 h70
  text "2" at 2923.54,-1698.4 h70
  text "3" at 5668.54,-1698.4 h70
  text "4" at 8419.55,-1698.4 h70

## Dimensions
-118.11,-118.11 to -118.11,3031.5 on Dimensions
-118.11,-118.11 to 4606.3,-118.11 on Dimensions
